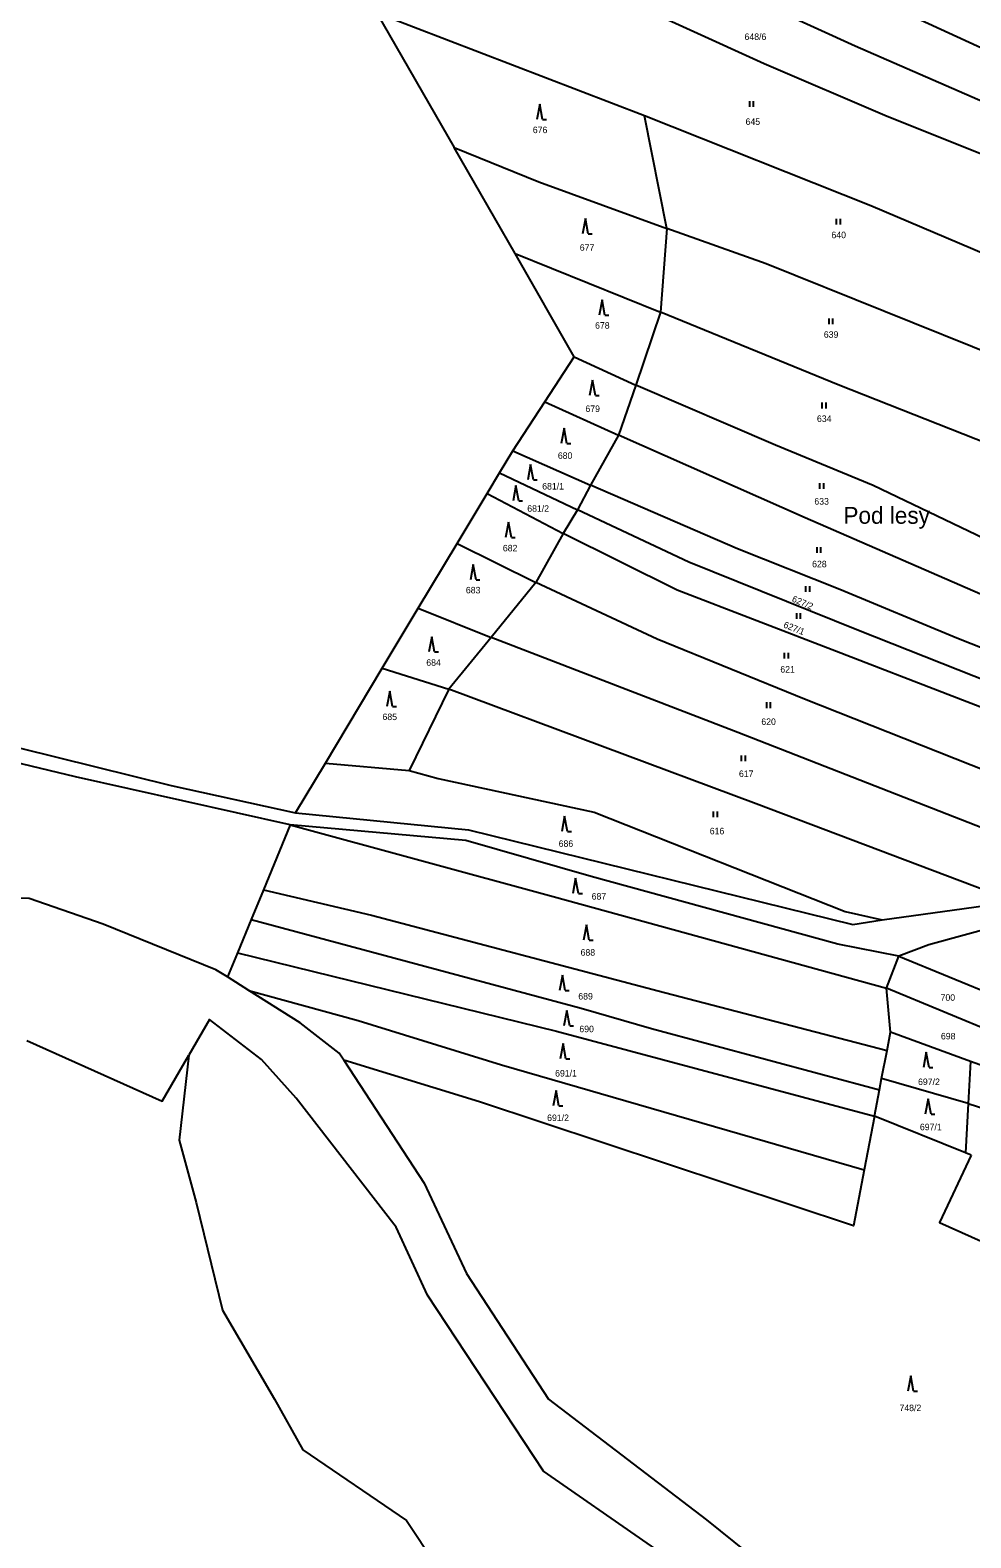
# Model space of a CAD drawing. Extents: x -751333 to -746055, y -1133395 to -1129777.
# Drawn here: x -748944.8 to -748699.3, y -1131157.3 to -1130763.6 of the extents above; entities that cross this region are included whole.
import ezdxf

# ---------------------------------------------------------------- set-up
doc = ezdxf.new("R2010")
doc.units = 0
for name, color, linetype in [('Hranice parcel', 7, 'Continuous'), ('Parcelní čísla', 7, 'Continuous'), ('Pop  PČ popisy', 7, 'Continuous'), ('Značky kultur', 7, 'Continuous')]:
    doc.layers.add(name, color=color, linetype=linetype)

msp = doc.modelspace()

# ---------------------------------------------------------------- linework, layer by layer
at = {"layer": 'Hranice parcel'}
for p, q in [((-748854.35, -1130759.21), (-748834.13, -1130794.29)), ((-748784.49, -1130785.99), (-748853.32, -1130759.59)), ((-748778.58, -1130815.45), (-748784.49, -1130785.99)), ((-748818.2, -1130821.92), (-748834.13, -1130794.29)), ((-748778.58, -1130815.45), (-748780.28, -1130837.27)), ((-748818.2, -1130821.92), (-748780.28, -1130837.27)), ((-748802.84, -1130848.91), (-748818.2, -1130821.92)), ((-748780.28, -1130837.27), (-748786.7, -1130856.35)), ((-748810.46, -1130860.65), (-748802.84, -1130848.91)), ((-748802.84, -1130848.91), (-748786.7, -1130856.35)), ((-748786.7, -1130856.35), (-748791.23, -1130869.37)), ((-748818.81, -1130873.52), (-748810.46, -1130860.65)), ((-748810.46, -1130860.65), (-748791.23, -1130869.37)), ((-748791.23, -1130869.37), (-748798.57, -1130882.46)), ((-748822.26, -1130879.25), (-748818.81, -1130873.52)), ((-748818.81, -1130873.52), (-748798.57, -1130882.46)), ((-748825.52, -1130884.67), (-748822.26, -1130879.25)), ((-748822.26, -1130879.25), (-748801.95, -1130888.88)), ((-748833.33, -1130897.65), (-748825.52, -1130884.67)), ((-748825.52, -1130884.67), (-748805.64, -1130895.06)), ((-748798.57, -1130882.46), (-748801.95, -1130888.88)), ((-748801.95, -1130888.88), (-748805.64, -1130895.06)), ((-748843.53, -1130914.6), (-748833.33, -1130897.65)), ((-748833.33, -1130897.65), (-748812.83, -1130907.88)), ((-748805.64, -1130895.06), (-748812.83, -1130907.88)), ((-748812.83, -1130907.88), (-748824.49, -1130922.2)), ((-748852.94, -1130930.24), (-748843.53, -1130914.6)), ((-748843.53, -1130914.6), (-748824.49, -1130922.2)), ((-748824.49, -1130922.2), (-748835.48, -1130935.7)), ((-748867.73, -1130955.03), (-748852.94, -1130930.24)), ((-748852.94, -1130930.24), (-748835.48, -1130935.7)), ((-748835.48, -1130935.7), (-748845.89, -1130956.91)), ((-748875.49, -1130968.04), (-748867.73, -1130955.03)), ((-748867.73, -1130955.03), (-748845.89, -1130956.91)), ((-748876.9, -1130971.17), (-748883.92, -1130988.13)), ((-748883.92, -1130988.13), (-748887.11, -1130995.84)), ((-748722.45, -1130995.95), (-748687.86, -1130991.16)), ((-748887.11, -1130995.84), (-748890.71, -1131004.53)), ((-748890.71, -1131004.53), (-748893.32, -1131010.83)), ((-748721.27, -1131013.77), (-748718.11, -1131005.41)), ((-748718.11, -1131005.41), (-748691.78, -1131016.23)), ((-748887.67, -1131014.39), (-748893.32, -1131010.83)), ((-748691.89, -1131026.01), (-748721.27, -1131013.77)), ((-748720.21, -1131025.25), (-748721.27, -1131013.77)), ((-748721.16, -1131030.03), (-748720.21, -1131025.25)), ((-748699.34, -1131032.91), (-748720.21, -1131025.25)), ((-748722.61, -1131037.34), (-748721.16, -1131030.03)), ((-748699.34, -1131032.91), (-748700.01, -1131043.9)), ((-748691.34, -1131035.8), (-748699.34, -1131032.91)), ((-748723.16, -1131040.37), (-748722.61, -1131037.34)), ((-748700.01, -1131043.9), (-748722.61, -1131037.34)), ((-748724.39, -1131047.18), (-748723.16, -1131040.37)), ((-748724.39, -1131047.18), (-748727.08, -1131061.25)), ((-748700.66, -1131056.76), (-748724.39, -1131047.18)), ((-748700.01, -1131043.9), (-748700.66, -1131056.76)), ((-748700.01, -1131043.9), (-748695.07, -1131045.45)), ((-748699.23, -1131057.41), (-748700.66, -1131056.76))]:
    msp.add_line(p, q, dxfattribs=at)
for points in [[(-748656.74, -1130787.3), (-748680.72, -1130775.54), (-748712.39, -1130761.05), (-748780.75, -1130728.31), (-748831.33, -1130705.07), (-748858.25, -1130692.59)], [(-748855.58, -1130710.12), (-748821.23, -1130726.15), (-748767.45, -1130750.32), (-748729.5, -1130767.78), (-748660.26, -1130797.97)], [(-748663.47, -1130808.22), (-748695.21, -1130796.54), (-748721.13, -1130786.22), (-748753.25, -1130772.41), (-748790.9, -1130755.21), (-748826.39, -1130739.6), (-748853.82, -1130727.9)], [(-748679.08, -1130829.15), (-748725.39, -1130809.48), (-748784.49, -1130785.99)], [(-748834.13, -1130794.29), (-748811.99, -1130803.26), (-748778.58, -1130815.45)], [(-748691.29, -1130849.38), (-748752.74, -1130824.68), (-748778.58, -1130815.45)], [(-748691.38, -1130873.01), (-748733.87, -1130856.25), (-748780.28, -1130837.27)], [(-748691.56, -1130898.44), (-748724.77, -1130882.55), (-748750.23, -1130872.02), (-748786.7, -1130856.35)], [(-748676.59, -1130919.71), (-748742.5, -1130891), (-748791.23, -1130869.37)], [(-748674.28, -1130933.73), (-748702.92, -1130922.4), (-748733.51, -1130909.72), (-748760.2, -1130899.08), (-748798.57, -1130882.46)], [(-748672.59, -1130942.59), (-748728.61, -1130920.39), (-748772.9, -1130902.53), (-748801.95, -1130888.88)], [(-748673.99, -1130949.21), (-748734.35, -1130925.92), (-748775.96, -1130909.83), (-748805.64, -1130895.06)], [(-748677.43, -1130964.14), (-748742.72, -1130938.33), (-748781.18, -1130922.64), (-748812.83, -1130907.88)], [(-748686.82, -1130975.66), (-748760.05, -1130947.07), (-748824.49, -1130922.2)], [(-748687.86, -1130991.16), (-748755.34, -1130965.63), (-748835.48, -1130935.7)], [(-749141.24, -1130998.34), (-749051.87, -1130972), (-749016.37, -1130960.85), (-748977.23, -1130943.74), (-748907.96, -1130960.85), (-748875.49, -1130968.04)], [(-748876.9, -1130971.17), (-748932.91, -1130958.6), (-748976.78, -1130948.06), (-749012.79, -1130966.3), (-749130.24, -1131001.82), (-749149.18, -1131007.85), (-749173.79, -1131015.01)], [(-748845.89, -1130956.91), (-748838.31, -1130959.08), (-748797.6, -1130967.82), (-748732.08, -1130993.78), (-748722.45, -1130995.95)], [(-748875.49, -1130968.04), (-748830.4, -1130972.44), (-748730.06, -1130997.2), (-748722.45, -1130995.95)], [(-748718.11, -1131005.41), (-748734.03, -1131002.28), (-748798.34, -1130984.6), (-748831.06, -1130975.19), (-748876.9, -1130971.17)], [(-748876.9, -1130971.17), (-748808.26, -1130989.85), (-748721.27, -1131013.77)], [(-748883.92, -1130988.13), (-748855.69, -1130994.76), (-748779.2, -1131014.91), (-748721.16, -1131030.03)], [(-748893.32, -1131010.83), (-748896.35, -1131008.97), (-748925.75, -1130997.04), (-748945.03, -1130990.41), (-748973.15, -1130989.2), (-748997.61, -1130990.29), (-749095.8, -1131010.5), (-749153.88, -1131013.75), (-749163.47, -1131013.27), (-749173.79, -1131015.01)], [(-748887.11, -1130995.84), (-748800.99, -1131019), (-748782.66, -1131024.35), (-748723.16, -1131040.37)], [(-748691.81, -1130997.44), (-748710.23, -1131002.5), (-748718.11, -1131005.41)], [(-748890.71, -1131004.53), (-748807.39, -1131024.98), (-748724.39, -1131047.18)], [(-748887.67, -1131014.39), (-748859.22, -1131022.19), (-748821.78, -1131033.78), (-748727.08, -1131061.25)], [(-748862.93, -1131032.61), (-748864.13, -1131030.78), (-748874.3, -1131022.82), (-748887.67, -1131014.39)], [(-748392.16, -1131506.55), (-748408.97, -1131492.45), (-748455.93, -1131466.65), (-748484.5, -1131445.39), (-748502.39, -1131429.25), (-748511.24, -1131427.32), (-748518.9, -1131418.34), (-748522.93, -1131412.38), (-748534.82, -1131400.07), (-748560.04, -1131371.4), (-748567.63, -1131359.17), (-748618.14, -1131307.59), (-748670.88, -1131247.89), (-748697.81, -1131219.81), (-748711.66, -1131216.37), (-748756.69, -1131177.5), (-748810.83, -1131139.93), (-748841.05, -1131093.93), (-748849.27, -1131076.16), (-748875.35, -1131042.49), (-748884.41, -1131032.45), (-748897.97, -1131021.96), (-748903.36, -1131031.29)], [(-748945.65, -1131027.42), (-748910.29, -1131043.26), (-748903.36, -1131031.29)], [(-748903.36, -1131031.29), (-748905.89, -1131053.47), (-748901.45, -1131069.76), (-748894.6, -1131097.89), (-748881.04, -1131121.08), (-748873.58, -1131134.34), (-748846.57, -1131152.8), (-748823.65, -1131187.26), (-748755.15, -1131237.08), (-748782.58, -1131345.17), (-748793.36, -1131398.73), (-748812.12, -1131488.8), (-748821.02, -1131580.29), (-748829.28, -1131664.88)], [(-748727.08, -1131061.25), (-748729.9, -1131075.88), (-748827.51, -1131043.45), (-748862.93, -1131032.61)], [(-748862.93, -1131032.61), (-748841.96, -1131064.7), (-748830.94, -1131088.32), (-748809.47, -1131121.13), (-748768.27, -1131152.58), (-748729.51, -1131183.85), (-748683.15, -1131218.97), (-748628.13, -1131281.36), (-748623.2, -1131281.94), (-748602.24, -1131308.39), (-748580.92, -1131332.73), (-748557.75, -1131353.82), (-748544.86, -1131363.16), (-748538.91, -1131375.03), (-748525.17, -1131390.76), (-748504.57, -1131408.29), (-748496.26, -1131416.91), (-748493.37, -1131423.24), (-748472.53, -1131441.85), (-748441.17, -1131464.36)], [(-748699.23, -1131057.41), (-748707.43, -1131074.93), (-748684.92, -1131085.04), (-748649.3, -1131104.79)]]:
    msp.add_lwpolyline(points, dxfattribs=at)
at = {"layer": 'Značky kultur'}
for p, q in [((-748811.81, -1130782.99), (-748812.56, -1130786.99)), ((-748811.06, -1130786.99), (-748811.81, -1130782.99)), ((-748757.001, -1130783.66), (-748757.001, -1130782.16)), ((-748756, -1130783.66), (-748756, -1130782.16)), ((-748811.06, -1130786.99), (-748810.064, -1130786.99)), ((-748799.88, -1130812.84), (-748800.63, -1130816.84)), ((-748799.13, -1130816.84), (-748799.88, -1130812.84)), ((-748734.321, -1130814.42), (-748734.321, -1130812.92)), ((-748733.32, -1130814.42), (-748733.32, -1130812.92)), ((-748799.13, -1130816.84), (-748798.134, -1130816.84)), ((-748795.53, -1130834.04), (-748796.28, -1130838.04)), ((-748794.78, -1130838.04), (-748795.53, -1130834.04)), ((-748794.78, -1130838.04), (-748793.784, -1130838.04)), ((-748736.261, -1130840.42), (-748736.261, -1130838.92)), ((-748735.26, -1130840.42), (-748735.26, -1130838.92)), ((-748798.03, -1130855.01), (-748798.78, -1130859.01)), ((-748797.28, -1130859.01), (-748798.03, -1130855.01)), ((-748797.28, -1130859.01), (-748796.284, -1130859.01)), ((-748738.061, -1130862.39), (-748738.061, -1130860.89)), ((-748737.06, -1130862.39), (-748737.06, -1130860.89)), ((-748805.45, -1130867.59), (-748806.2, -1130871.59)), ((-748804.7, -1130871.59), (-748805.45, -1130867.59)), ((-748804.7, -1130871.59), (-748803.704, -1130871.59)), ((-748814.17, -1130877.06), (-748814.92, -1130881.06)), ((-748813.42, -1130881.06), (-748814.17, -1130877.06)), ((-748813.42, -1130881.06), (-748812.424, -1130881.06)), ((-748738.651, -1130883.41), (-748738.651, -1130881.91)), ((-748737.65, -1130883.41), (-748737.65, -1130881.91)), ((-748818.01, -1130882.56), (-748818.76, -1130886.56)), ((-748817.26, -1130886.56), (-748818.01, -1130882.56)), ((-748817.26, -1130886.56), (-748816.264, -1130886.56)), ((-748819.95, -1130892.15), (-748820.7, -1130896.15)), ((-748819.2, -1130896.15), (-748819.95, -1130892.15)), ((-748819.2, -1130896.15), (-748818.204, -1130896.15)), ((-748739.421, -1130900.16), (-748739.421, -1130898.66)), ((-748738.42, -1130900.16), (-748738.42, -1130898.66)), ((-748829.14, -1130903.16), (-748829.89, -1130907.16)), ((-748828.39, -1130907.16), (-748829.14, -1130903.16)), ((-748828.39, -1130907.16), (-748827.394, -1130907.16)), ((-748742.311, -1130910.29), (-748742.311, -1130908.79)), ((-748741.31, -1130910.29), (-748741.31, -1130908.79)), ((-748744.721, -1130917.33), (-748744.721, -1130915.83)), ((-748743.72, -1130917.33), (-748743.72, -1130915.83)), ((-748839.99, -1130922.01), (-748840.74, -1130926.01)), ((-748839.24, -1130926.01), (-748839.99, -1130922.01)), ((-748839.24, -1130926.01), (-748838.244, -1130926.01)), ((-748747.871, -1130927.73), (-748747.871, -1130926.23)), ((-748746.87, -1130927.73), (-748746.87, -1130926.23)), ((-748850.94, -1130936.24), (-748851.69, -1130940.24)), ((-748850.19, -1130940.24), (-748850.94, -1130936.24)), ((-748850.19, -1130940.24), (-748849.194, -1130940.24)), ((-748752.561, -1130940.64), (-748752.561, -1130939.14)), ((-748751.56, -1130940.64), (-748751.56, -1130939.14)), ((-748759.121, -1130954.53), (-748759.121, -1130953.03)), ((-748758.12, -1130954.53), (-748758.12, -1130953.03)), ((-748766.411, -1130969.18), (-748766.411, -1130967.68)), ((-748765.41, -1130969.18), (-748765.41, -1130967.68)), ((-748805.29, -1130968.86), (-748806.04, -1130972.86)), ((-748804.54, -1130972.86), (-748805.29, -1130968.86)), ((-748804.54, -1130972.86), (-748803.544, -1130972.86)), ((-748802.42, -1130985.04), (-748803.17, -1130989.04)), ((-748801.67, -1130989.04), (-748802.42, -1130985.04)), ((-748801.67, -1130989.04), (-748800.674, -1130989.04)), ((-748799.63, -1130997.26), (-748800.38, -1131001.26)), ((-748798.88, -1131001.26), (-748799.63, -1130997.26)), ((-748798.88, -1131001.26), (-748797.884, -1131001.26)), ((-748805.87, -1131010.37), (-748806.62, -1131014.37)), ((-748805.12, -1131014.37), (-748805.87, -1131010.37)), ((-748805.12, -1131014.37), (-748804.124, -1131014.37)), ((-748804.73, -1131019.62), (-748805.48, -1131023.62)), ((-748803.98, -1131023.62), (-748804.73, -1131019.62)), ((-748803.98, -1131023.62), (-748802.984, -1131023.62)), ((-748805.7, -1131028.22), (-748806.45, -1131032.22)), ((-748804.95, -1131032.22), (-748805.7, -1131028.22)), ((-748710.92, -1131030.46), (-748711.67, -1131034.46)), ((-748710.17, -1131034.46), (-748710.92, -1131030.46)), ((-748804.95, -1131032.22), (-748803.954, -1131032.22)), ((-748710.17, -1131034.46), (-748709.174, -1131034.46)), ((-748807.54, -1131040.51), (-748808.29, -1131044.51)), ((-748806.79, -1131044.51), (-748807.54, -1131040.51)), ((-748710.43, -1131042.69), (-748711.18, -1131046.69)), ((-748709.68, -1131046.69), (-748710.43, -1131042.69)), ((-748806.79, -1131044.51), (-748805.794, -1131044.51)), ((-748709.68, -1131046.69), (-748708.684, -1131046.69)), ((-748714.97, -1131114.97), (-748715.72, -1131118.97)), ((-748714.22, -1131118.97), (-748714.97, -1131114.97)), ((-748714.22, -1131118.97), (-748713.224, -1131118.97))]:
    msp.add_line(p, q, dxfattribs=at)

# ---------------------------------------------------------------- texts
at = {"layer": 'Parcelní čísla'}
for s, p in [('648/6', (-748758.34, -1130766.21)), ('645', (-748758.07, -1130788.38)), ('676', (-748813.6, -1130790.54)), ('640', (-748735.66, -1130817.97)), ('677', (-748801.34, -1130821.26)), ('678', (-748797.35, -1130841.59)), ('639', (-748737.65, -1130843.97)), ('679', (-748799.87, -1130863.34)), ('634', (-748739.45, -1130865.94)), ('680', (-748807.06, -1130875.58)), ('681/1', (-748811.15, -1130883.59)), ('633', (-748740.12, -1130887.53)), ('681/2', (-748815.05, -1130889.4)), ('682', (-748821.42, -1130899.74)), ('628', (-748740.7, -1130903.89)), ('683', (-748831.07, -1130910.71)), ('684', (-748841.4, -1130929.61)), ('621', (-748749, -1130931.4)), ('685', (-748852.83, -1130943.79)), ('620', (-748753.96, -1130945.06)), ('617', (-748759.8, -1130958.65)), ('616', (-748767.42, -1130973.61)), ('686', (-748806.85, -1130976.9)), ('687', (-748798.24, -1130990.66)), ('688', (-748801.13, -1131005.3)), ('689', (-748801.73, -1131016.75)), ('700', (-748707.18, -1131017.08)), ('690', (-748801.45, -1131025.29)), ('698', (-748707.09, -1131027.17)), ('691/1', (-748807.78, -1131036.86)), ('697/2', (-748713.06, -1131039.08)), ('691/2', (-748809.86, -1131048.48)), ('697/1', (-748712.58, -1131050.88)), ('748/2', (-748717.91, -1131124.23))]:
    msp.add_text(s, height=1.7, dxfattribs=at).set_placement(p)
for s, rotation, p in [('627/2', 337, (-748746.142, -1130912.782)), ('627/1', 338, (-748748.358, -1130919.518))]:
    msp.add_text(s, height=1.7, rotation=rotation, dxfattribs=at).set_placement(p)
at = {"layer": 'Pop  PČ popisy'}
msp.add_text('Pod lesy', height=4.4, dxfattribs=at).set_placement((-748732.536, -1130892.53))

doc.saveas('drawing.dxf')
